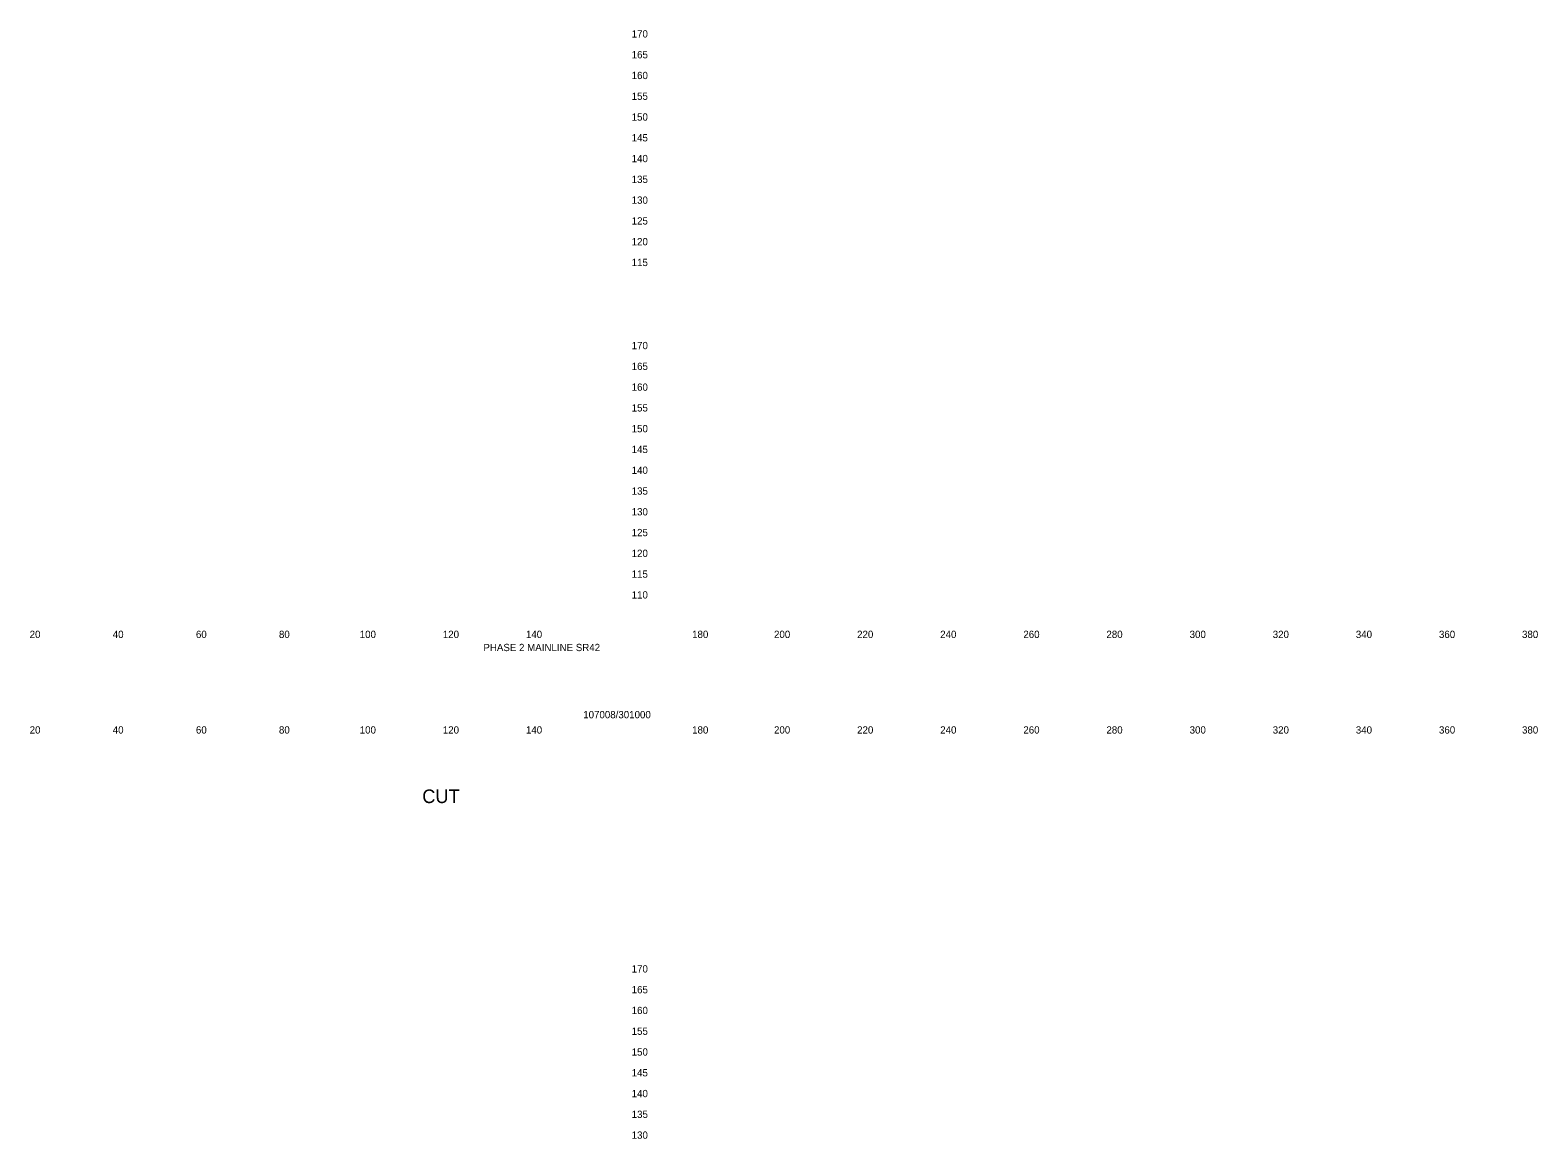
# Model space of a CAD drawing. Extents: x 21281 to 22024, y 6472 to 15208.
# Drawn here: x 21661.4 to 22024.2, y 13024.8 to 13291.6 of the extents above; entities that cross this region are included whole.
import ezdxf

# ---------------------------------------------------------------- set-up
doc = ezdxf.new("R2010")
doc.units = 0
doc.layers.add('XS_SHEET_LABELS_ELEVATION', color=7, linetype='Continuous')
doc.layers.add('XS_SHEET_LABELS_OFFSET', color=7, linetype='Continuous')

msp = doc.modelspace()

# ---------------------------------------------------------------- texts
at = {"layer": 'XS_SHEET_LABELS_ELEVATION'}
for s, p in [('  170  ', (21804.84, 13289.84)), ('  165  ', (21804.84, 13284.84)), ('  160  ', (21804.84, 13279.84)), ('  155  ', (21804.84, 13274.84)), ('  150  ', (21804.84, 13269.84)), ('  145  ', (21804.84, 13264.84)), ('  140  ', (21804.84, 13259.84)), ('  135  ', (21804.84, 13254.84)), ('  130  ', (21804.84, 13249.84)), ('  125  ', (21804.84, 13244.84)), ('  120  ', (21804.84, 13239.84)), ('  115  ', (21804.84, 13234.84)), ('  170  ', (21804.84, 13214.84)), ('  165  ', (21804.84, 13209.84)), ('  160  ', (21804.84, 13204.84)), ('  155  ', (21804.84, 13199.84)), ('  150  ', (21804.84, 13194.84)), ('  145  ', (21804.84, 13189.84)), ('  140  ', (21804.84, 13184.84)), ('  135  ', (21804.84, 13179.84)), ('  130  ', (21804.84, 13174.84)), ('  125  ', (21804.84, 13169.84)), ('  120  ', (21804.84, 13164.84)), ('  115  ', (21804.84, 13159.84)), ('  110  ', (21804.84, 13154.84)), ('  170  ', (21804.84, 13064.84)), ('  165  ', (21804.84, 13059.84)), ('  160  ', (21804.84, 13054.84)), ('  155  ', (21804.84, 13049.84)), ('  150  ', (21804.84, 13044.84)), ('  145  ', (21804.84, 13039.84)), ('  140  ', (21804.84, 13034.84)), ('  135  ', (21804.84, 13029.84)), ('  130  ', (21804.84, 13024.84))]:
    msp.add_text(s, height=1.75, dxfattribs=at).set_placement(p)
at = {"layer": 'XS_SHEET_LABELS_OFFSET'}
for s, height, p in [('  20  ', 1.75, (21659.95, 13145.34)), ('  40  ', 1.75, (21679.95, 13145.34)), ('  60  ', 1.75, (21699.97, 13145.34)), ('  80  ', 1.75, (21719.95, 13145.34)), ('  100  ', 1.75, (21739.39, 13145.34)), ('  120  ', 1.75, (21759.39, 13145.34)), ('  140  ', 1.75, (21779.39, 13145.34)), ('  180  ', 1.75, (21819.39, 13145.34)), ('  200  ', 1.75, (21839.1, 13145.34)), ('  220  ', 1.75, (21859.1, 13145.34)), ('  240  ', 1.75, (21879.1, 13145.34)), ('  260  ', 1.75, (21899.11, 13145.34)), ('  280  ', 1.75, (21919.1, 13145.34)), ('  300  ', 1.75, (21939.13, 13145.34)), ('  320  ', 1.75, (21959.13, 13145.34)), ('  340  ', 1.75, (21979.13, 13145.34)), ('  360  ', 1.75, (21999.14, 13145.34)), ('  380  ', 1.75, (22019.13, 13145.34)), ('PHASE 2 MAINLINE SR42', 1.75, (21770.45, 13142.18)), ('107008/301000', 1.75, (21794.48, 13126.02)), ('  20  ', 1.75, (21659.95, 13122.34)), ('  40  ', 1.75, (21679.95, 13122.34)), ('  60  ', 1.75, (21699.97, 13122.34)), ('  80  ', 1.75, (21719.95, 13122.34)), ('  100  ', 1.75, (21739.39, 13122.34)), ('  120  ', 1.75, (21759.39, 13122.34)), ('  140  ', 1.75, (21779.39, 13122.34)), ('  180  ', 1.75, (21819.39, 13122.34)), ('  200  ', 1.75, (21839.1, 13122.34)), ('  220  ', 1.75, (21859.1, 13122.34)), ('  240  ', 1.75, (21879.1, 13122.34)), ('  260  ', 1.75, (21899.11, 13122.34)), ('  280  ', 1.75, (21919.1, 13122.34)), ('  300  ', 1.75, (21939.13, 13122.34)), ('  320  ', 1.75, (21959.13, 13122.34)), ('  340  ', 1.75, (21979.13, 13122.34)), ('  360  ', 1.75, (21999.14, 13122.34)), ('  380  ', 1.75, (22019.13, 13122.34)), ('CUT', 3.273, (21755.74, 13105.61))]:
    msp.add_text(s, height=height, dxfattribs=at).set_placement(p)

doc.saveas('drawing.dxf')
